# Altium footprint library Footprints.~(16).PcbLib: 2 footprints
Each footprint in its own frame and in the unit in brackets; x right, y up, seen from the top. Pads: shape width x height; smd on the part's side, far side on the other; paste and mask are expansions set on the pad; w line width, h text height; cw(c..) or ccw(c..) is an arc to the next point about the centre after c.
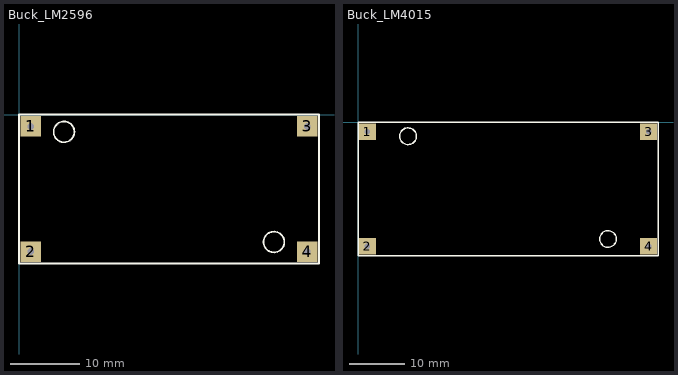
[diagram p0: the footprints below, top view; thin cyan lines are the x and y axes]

## Buck_LM2596 [mm]
height 11.5
pads (4):
  rect 3x3 hole 1: 1(1.7,-1.7) 2(1.7,-19.8) 3(41.6,-1.7) 4(41.6,-19.8)
Top Overlay:
  circle w0.254: c6.5,-2.5 r1.5
  circle w0.254: c36.8,-18.4 r1.5
  lines w0.254: 0,-21.5 0,0 43.3,0 43.3,-21.5 0,-21.5

## Buck_LM4015 [mm]
height 11.5
pads (4):
  rect 3x3 hole 1: 1(1.7,-1.7) 2(1.7,-22.3) 3(52.3,-1.7) 4(52.3,-22.3)
Top Overlay:
  circle w0.254: c45,-21 r1.5
  circle w0.254: c9,-2.5 r1.5
  lines w0.254: 0,-24 0,0 54,0 54,-24 0,-24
